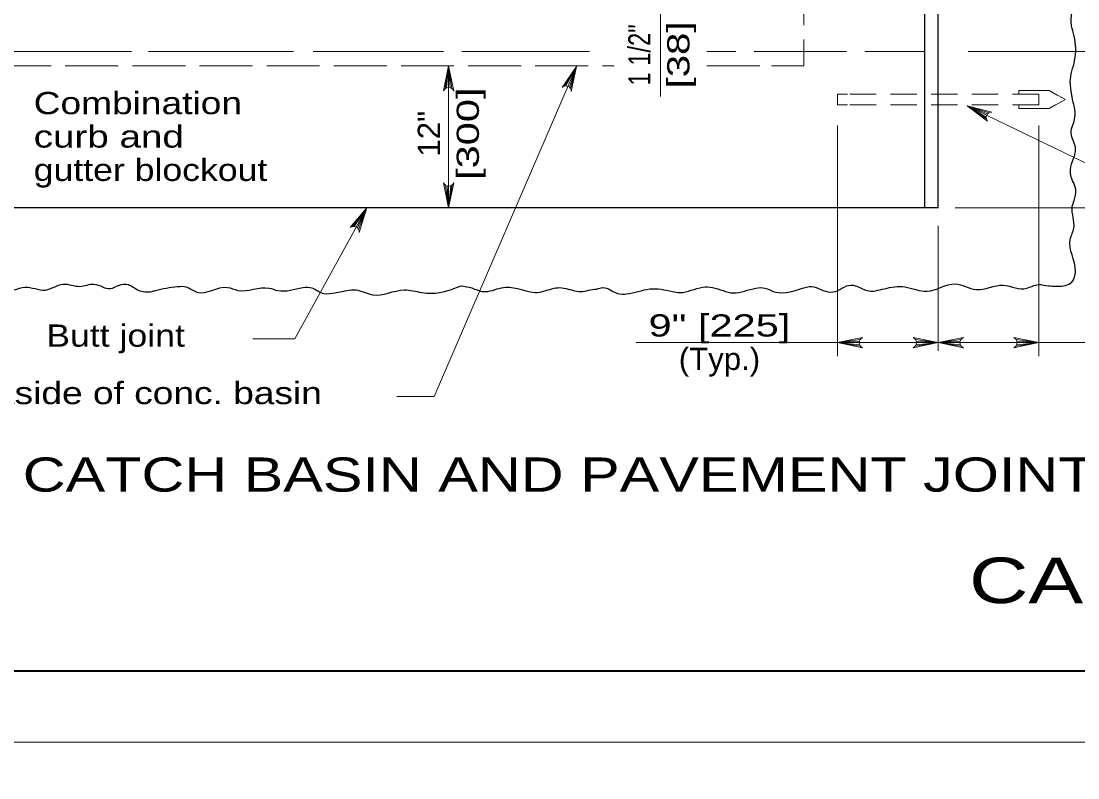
# Model space of a CAD drawing. Extents: x 1352.5 to 1386.5, y 735.9 to 779.9.
# Drawn here: x 1360.33 to 1367.76, y 757.67 to 762.99 of the extents above; entities that cross this region are included whole.
import ezdxf
from ezdxf.enums import TextEntityAlignment as Align

# ---------------------------------------------------------------- set-up
doc = ezdxf.new("R2010")
doc.units = 0
doc.header["$LTSCALE"] = 0.062
doc.linetypes.add('LONG_DASHED', pattern=[7.5, 6, -1.5])
doc.linetypes.add('MEDIUM_DASHED', pattern=[4.5, 3, -1.5])
doc.layers.add('1', color=7, linetype='Continuous', lineweight=13)

msp = doc.modelspace()

# ---------------------------------------------------------------- linework, layer by layer
at = {"layer": '1', "lineweight": 25}
for p, q in [((1366.78067, 761.67433), (1366.78067, 764.26117)), ((1366.68625, 761.67433), (1366.68625, 763.03533))]:
    msp.add_line(p, q, dxfattribs=at)
at = {"layer": '1'}
for p, q in [((1364.828, 762.45833), (1364.828, 763.27342)), ((1365.83667, 762.67375), (1365.83667, 762.85042)), ((1360.24875, 762.77367), (1361.10942, 762.77367)), ((1361.22975, 762.77367), (1362.24783, 762.77367)), ((1362.38667, 762.77367), (1363.30292, 762.77367)), ((1363.4325, 762.77367), (1364.33017, 762.77367)), ((1365.155, 762.77367), (1365.3575, 762.77367)), ((1365.48708, 762.77367), (1366.135, 762.77367)), ((1366.2645, 762.77367), (1366.68625, 762.77367)), ((1366.99225, 762.77367), (1371.64892, 762.77367)), ((1363.31467, 762.51167), (1363.3395, 762.67375)), ((1363.32508, 762.51775), (1363.3395, 762.67375)), ((1363.3395, 762.67375), (1363.3395, 762.03192)), ((1363.3395, 762.52058), (1363.3395, 762.67375)), ((1363.35075, 762.51892), (1363.3395, 762.67375)), ((1363.36192, 762.5135), (1363.3395, 762.67375)), ((1364.152, 762.53017), (1364.239, 762.66917)), ((1364.16392, 762.53167), (1364.239, 762.66917)), ((1364.17825, 762.52858), (1364.239, 762.66917)), ((1364.188, 762.52258), (1364.239, 762.66917)), ((1364.19608, 762.51317), (1364.239, 762.66917)), ((1365.83667, 762.67375), (1365.60917, 762.67375)), ((1366.07267, 762.47383), (1366.07267, 762.39892)), ((1366.14392, 762.47383), (1366.07267, 762.47383)), ((1367.34708, 762.47383), (1367.34708, 762.49883)), ((1367.5595, 762.49883), (1367.46658, 762.49883)), ((1367.48867, 762.39892), (1367.48867, 762.47383)), ((1367.5595, 762.49883), (1367.61783, 762.46717)), ((1366.14392, 762.39892), (1366.07267, 762.39892)), ((1367.34708, 762.39892), (1367.34708, 762.37392)), ((1367.5595, 762.37392), (1367.60583, 762.39917)), ((1367.12183, 762.32583), (1366.98408, 762.39283)), ((1367.11808, 762.31167), (1366.98408, 762.39283)), ((1367.11908, 762.29967), (1366.98408, 762.39283)), ((1367.12825, 762.33533), (1366.98408, 762.39283)), ((1367.138, 762.34292), (1366.98408, 762.39283)), ((1367.5595, 762.37392), (1367.48208, 762.37392)), ((1366.07267, 762.25467), (1366.07267, 760.63283)), ((1367.48867, 762.25467), (1367.48867, 760.63283)), ((1363.3395, 762.03192), (1363.3395, 761.67433)), ((1363.317, 761.83458), (1363.3395, 761.67433)), ((1363.32817, 761.82917), (1363.3395, 761.67433)), ((1363.36425, 761.8365), (1363.3395, 761.67433)), ((1363.35383, 761.83033), (1363.3395, 761.67433)), ((1363.3395, 761.8275), (1363.3395, 761.67433)), ((1362.76417, 761.6745), (1362.25867, 760.75517)), ((1362.66433, 761.54442), (1362.76417, 761.6745)), ((1362.67633, 761.54483), (1362.76417, 761.6745)), ((1362.69025, 761.54033), (1362.76417, 761.6745)), ((1362.69942, 761.53342), (1362.76417, 761.6745)), ((1362.70658, 761.52333), (1362.76417, 761.6745)), ((1366.89875, 761.67433), (1371.63117, 761.67433)), ((1366.78067, 761.54917), (1366.78067, 760.66925)), ((1362.25867, 760.75517), (1361.964, 760.75517)), ((1366.23292, 760.75008), (1366.07267, 760.72767)), ((1366.2275, 760.739), (1366.07267, 760.72767)), ((1366.22583, 760.72767), (1366.07267, 760.72767)), ((1366.22867, 760.71325), (1366.07267, 760.72767)), ((1366.23483, 760.70292), (1366.07267, 760.72767)), ((1366.6185, 760.70292), (1366.78067, 760.72767)), ((1366.62042, 760.75008), (1366.78067, 760.72767)), ((1366.62467, 760.71325), (1366.78067, 760.72767)), ((1366.62583, 760.739), (1366.78067, 760.72767)), ((1366.6275, 760.72767), (1366.78067, 760.72767)), ((1366.94092, 760.75008), (1366.78067, 760.72767)), ((1366.9355, 760.739), (1366.78067, 760.72767)), ((1366.78067, 760.72767), (1368.79867, 760.72767)), ((1366.93383, 760.72767), (1366.78067, 760.72767)), ((1366.93667, 760.71325), (1366.78067, 760.72767)), ((1366.94283, 760.70292), (1366.78067, 760.72767)), ((1367.2655, 760.72767), (1367.48867, 760.72767)), ((1367.3265, 760.70292), (1367.48867, 760.72767)), ((1367.32842, 760.75008), (1367.48867, 760.72767)), ((1367.33267, 760.71325), (1367.48867, 760.72767)), ((1367.33383, 760.739), (1367.48867, 760.72767)), ((1367.3355, 760.72767), (1367.48867, 760.72767))]:
    msp.add_line(p, q, dxfattribs=at)
at = {"layer": '1', "linetype": 'LONG_DASHED'}
for p, q in [((1360.17267, 762.67375), (1364.50358, 762.67375)), ((1365.155, 762.67375), (1365.83667, 762.67375))]:
    msp.add_line(p, q, dxfattribs=at)
at = {"layer": '1', "linetype": 'MEDIUM_DASHED'}
for p, q in [((1367.48867, 762.47383), (1366.07267, 762.47383)), ((1367.34708, 762.49883), (1367.5595, 762.49883)), ((1367.67442, 762.43642), (1367.5595, 762.49883)), ((1367.48867, 762.39892), (1366.07267, 762.39892)), ((1367.67442, 762.43642), (1367.5595, 762.37392)), ((1367.34708, 762.37392), (1367.5595, 762.37392))]:
    msp.add_line(p, q, dxfattribs=at)
at = {"layer": '1', "linetype": 'LONG_DASHED'}
for points in [[(1352.513, 757.91967), (1386.513, 757.91967), (1386.513, 779.91967), (1352.513, 779.91967)], [(1352.513, 735.91967), (1386.513, 735.91967), (1386.513, 757.91967), (1352.513, 757.91967)]]:
    msp.add_lwpolyline(points, close=True, dxfattribs=at)
at = {"layer": '1', "lineweight": 25}
for points in [[(1386.013, 758.41967), (1354.513, 758.41967), (1354.513, 779.41967)], [(1366.78067, 761.67433), (1359.22867, 761.67433), (1359.22867, 765.17233)]]:
    msp.add_lwpolyline(points, dxfattribs=at)
at = {"layer": '1', "lineweight": 40}
msp.add_lwpolyline([(1354.513, 779.41967), (1386.013, 779.41967), (1386.013, 758.41967), (1354.513, 758.41967)], close=True, dxfattribs=at)
msp.add_lwpolyline([(1354.513, 779.41967), (1386.013, 779.41967), (1386.013, 758.41967), (1354.513, 758.41967)], close=True, dxfattribs=at)
at = {"layer": '1', "linetype": 'LONG_DASHED'}
msp.add_lwpolyline([(1365.83667, 764.77258), (1365.83667, 764.27483), (1365.83667, 762.67375)], dxfattribs=at)
at = {"layer": '1'}
for points in [[(1364.239, 762.66917), (1363.23867, 760.34925), (1362.975, 760.34925)], [(1363.30408, 762.49675), (1363.3395, 762.67375), (1363.37483, 762.49675)], [(1364.13633, 762.52075), (1364.239, 762.66917), (1364.20133, 762.49267)], [(1366.98408, 762.39283), (1367.94567, 761.92742), (1368.20933, 761.92742)], [(1367.12783, 762.28358), (1366.98408, 762.39283), (1367.15875, 762.34725)], [(1363.37483, 761.85133), (1363.3395, 761.67433), (1363.30408, 761.85133)], [(1362.64783, 761.53658), (1362.76417, 761.6745), (1362.70983, 761.50242)], [(1366.24967, 760.69225), (1366.07267, 760.72767), (1366.24967, 760.76308)], [(1366.60367, 760.69225), (1366.78067, 760.72767), (1366.60367, 760.76308)], [(1366.95767, 760.69225), (1366.78067, 760.72767), (1366.95767, 760.76308)], [(1367.31167, 760.69225), (1367.48867, 760.72767), (1367.31167, 760.76308)], [(1364.65775, 760.72767), (1366.53642, 760.72767), (1366.78067, 760.72767)]]:
    msp.add_lwpolyline(points, dxfattribs=at)
for centre, start, end in [((1363.3395, 762.48246), 22.08782, 157.91395), ((1364.1632, 762.49354), 358.73487, 134.56099), ((1367.15614, 762.30921), 86.15864, 221.98477), ((1363.33942, 761.86563), 202.08782, 337.91395), ((1362.67195, 761.50691), 353.2579, 129.08403), ((1366.26397, 760.72773), 112.08782, 247.91395), ((1366.58938, 760.72773), 292.08605, 67.91218), ((1366.97197, 760.72773), 112.08782, 247.91395), ((1367.29738, 760.72773), 292.08605, 67.91218)]:
    msp.add_arc(centre, 0.0382, start, end, dxfattribs=at)
at = {"layer": '1', "lineweight": 25}
for points in [[(1358.28467, 765.17233), (1358.27392, 765.12667), (1358.2975, 765.03625), (1358.28183, 764.97875), (1358.263, 764.8895), (1358.2955, 764.75042), (1358.29975, 764.70767), (1358.27567, 764.65417), (1358.30367, 764.527), (1358.276, 764.413), (1358.29917, 764.27292), (1358.27708, 764.15292), (1358.308, 764.03467), (1358.2615, 763.91375), (1358.30475, 763.80333), (1358.30933, 763.79042), (1358.28633, 763.67242), (1358.307, 763.56908), (1358.30733, 763.5055), (1358.26458, 763.39358), (1358.2765, 763.35383), (1358.31542, 763.28217), (1358.33125, 763.166), (1358.2845, 763.03125), (1358.26858, 762.95183), (1358.2935, 762.80483), (1358.2925, 762.70558), (1358.27417, 762.57167), (1358.29075, 762.43958), (1358.27958, 762.36417), (1358.30842, 762.236), (1358.29917, 762.16067), (1358.29425, 762.13983), (1358.30233, 762.00375), (1358.26642, 761.91058), (1358.28425, 761.722), (1358.26283, 761.65158), (1358.28, 761.586), (1358.3085, 761.50242), (1358.29175, 761.34075), (1358.2805, 761.25842), (1358.29475, 761.17592), (1358.35658, 761.13), (1358.51342, 761.13717), (1358.55292, 761.12108), (1358.56608, 761.11508), (1358.63575, 761.09783), (1358.76925, 761.133), (1358.85692, 761.11367), (1358.89675, 761.13533), (1358.97408, 761.129), (1359.03258, 761.11875), (1359.12533, 761.14317), (1359.181, 761.13592), (1359.29192, 761.09167), (1359.431, 761.11583), (1359.51567, 761.08167), (1359.62733, 761.11192), (1359.73958, 761.09942), (1359.86158, 761.11775), (1359.87758, 761.11667), (1359.968, 761.08742), (1360.04842, 761.10192), (1360.08075, 761.12558), (1360.16192, 761.12125), (1360.21442, 761.09217), (1360.28625, 761.09775), (1360.36108, 761.11825), (1360.50533, 761.09767), (1360.6295, 761.13883), (1360.74825, 761.12333), (1360.84658, 761.13875), (1360.96342, 761.10742), (1361.01933, 761.13), (1361.08833, 761.13558), (1361.15683, 761.0975), (1361.255, 761.08808), (1361.27867, 761.09392), (1361.43375, 761.122), (1361.49517, 761.11967), (1361.53275, 761.10167), (1361.57025, 761.08258), (1361.784, 761.11633), (1361.85842, 761.09508), (1362.07767, 761.11092), (1362.13883, 761.09375), (1362.31467, 761.11475), (1362.37792, 761.11242), (1362.4625, 761.07225), (1362.54092, 761.07883), (1362.56267, 761.08175), (1362.68658, 761.099), (1362.80325, 761.06467), (1363.02833, 761.09833), (1363.14808, 761.08083), (1363.22175, 761.07458), (1363.42808, 761.12617)], [(1363.42808, 761.12617), (1363.5015, 761.11192), (1363.58433, 761.08667), (1363.71025, 761.11292), (1363.82258, 761.10842), (1363.96392, 761.08083), (1364.08033, 761.11008), (1364.13517, 761.11383), (1364.25383, 761.08742), (1364.36542, 761.10275), (1364.38058, 761.10467), (1364.42317, 761.11442), (1364.52667, 761.07417), (1364.59075, 761.06992), (1364.7535, 761.10483), (1364.913, 761.08817), (1364.96483, 761.08), (1365.12567, 761.11792), (1365.19458, 761.11558), (1365.34058, 761.07717), (1365.49958, 761.11117), (1365.56283, 761.11083), (1365.62867, 761.08567), (1365.85458, 761.11733), (1365.87358, 761.12125), (1366.00542, 761.08483), (1366.0735, 761.09242), (1366.13517, 761.12592), (1366.1975, 761.12758), (1366.28025, 761.09342), (1366.40317, 761.10675), (1366.54583, 761.11992), (1366.70225, 761.08842), (1366.90017, 761.14008), (1367.04608, 761.10167), (1367.23808, 761.1315), (1367.32383, 761.11317), (1367.40117, 761.10983), (1367.48458, 761.13625), (1367.55625, 761.126), (1367.5685, 761.12592), (1367.6195, 761.12367), (1367.71983, 761.153), (1367.74517, 761.22825), (1367.70875, 761.45275), (1367.73417, 761.53308), (1367.72342, 761.68), (1367.73617, 761.72667), (1367.74733, 761.803), (1367.7125, 761.90333), (1367.71708, 761.98183), (1367.7465, 762.08583), (1367.71558, 762.20308), (1367.74217, 762.31125), (1367.72192, 762.45425), (1367.71925, 762.47008), (1367.70883, 762.5615), (1367.73958, 762.71125), (1367.73667, 762.882), (1367.7185, 762.95358), (1367.73758, 763.158), (1367.73775, 763.25817), (1367.71267, 763.39033), (1367.689, 763.57608), (1367.71, 763.68717), (1367.70975, 763.74067)]]:
    msp.add_spline(points, degree=3, dxfattribs=at)

# ---------------------------------------------------------------- texts
at = {"layer": '1'}
for s, width, p in [('1 1/2"', 0.8, (1364.758, 762.74929)), ('[38]', 1.35, (1365.032, 762.74925)), ('[300]', 1.4, (1363.55217, 762.19575)), ('12"', 1.05, (1363.27817, 762.19575))]:
    msp.add_text(s, height=0.156, rotation=90, dxfattribs=dict(at, width=width)).set_placement(p, align=Align.CENTER)
for s, height, width, p in [('Combination', 0.156, 1.25, (1360.42292, 762.33317)), ('curb and', 0.156, 1.3, (1360.42292, 762.0985)), ('gutter blockout', 0.156, 1.2, (1360.42292, 761.86383)), ('Butt joint', 0.156, 1.2, (1360.51125, 760.6995)), ('Outside of conc. basin', 0.156, 1.25, (1359.86817, 760.29575)), ('PLAN OF CATCH BASIN AND PAVEMENT JOINTS', 0.24, 1.3, (1358.44475, 759.68083))]:
    msp.add_text(s, height=height, dxfattribs=dict(at, width=width)).set_placement(p)
for s, width, p in [('9" [225]', 1.4, (1365.24296, 760.77067)), ('(Typ.)', 1.05, (1365.24304, 760.536))]:
    msp.add_text(s, height=0.156, dxfattribs=dict(at, width=width)).set_placement(p, align=Align.CENTER)
at = {"layer": '1', "width": 1.35}
msp.add_text('CATCH BASIN No. 3', height=0.32, rotation=359.766, dxfattribs=at).set_placement((1366.997, 758.89842))

doc.saveas('drawing.dxf')
